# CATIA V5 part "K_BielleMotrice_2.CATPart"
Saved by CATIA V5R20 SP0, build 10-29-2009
Part number: Bielle_motrice_2
Bounding box of the stored display mesh (mm): x -195 to -75, y -122.303 to -107.303, z -65 to -35
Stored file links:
  G:\Khaled_CFAO_2011\ST2M\ST2M_GR2\jcoetard\Khaled\CAD_CATIA\K_BielleMotrice_2.CATPart
  J:\Thinkmotion\Thinkmotion_COETARD\Maquette_catia\Maquette_catia_R20_Licence_education\jcharlescoetard.CATPRODUCT\Assemblage_Pince_Prehension_Mors_Paralleles.CATProduct
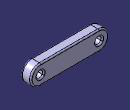
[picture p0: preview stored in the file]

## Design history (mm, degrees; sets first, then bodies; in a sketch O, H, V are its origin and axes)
Set1
  Plane1 "Plan_bielle_motrice": linked copy from another document
  Point1 "Point.11": linked copy from another document
  Point2 "Point.12": linked copy from another document
Body1 (main body)
  Sketch1 on Plane1, origin (0, -107.303, 0), H (-1, 0, 0), V (0, 0, 1)
    construction line L1 (90, -50) -> (180, -50)
    point P1 (90, -50)
    point P2 (180, -50)
    line L2 (90, -35) -> (180, -35)
    line L3 (180, -65) -> (90, -65)
    arc A1 centre (180, -50) radius 15 from (180, -35) to (180, -65) cw
    arc A2 centre (90, -50) radius 15 from (90, -65) to (90, -35) cw
    reference projected point E1 (180, -50) from Point2
    reference projected point E2 (90, -50) from Point1
    distance L2 L3 = 30
    tangency: A1 L2, A2 L2, A1 L3, A2 L3
    coincidence: P2 E1, P1 E2
  Pad1: profile Sketch1, direction (0, -1, 0), length 15
  Sketch2 on start face of Pad1, origin (-40, -107.303, -33.3333), H (1, 0, 0), V (0, 0, -1)
    point P1 (-50, 16.6667)
    reference projected point E1 (-50, 16.6667) from Point1
    coincidence: E1 P1
  Hole1: placed by Sketch2, at (-90, -107.303, -50) direction (0, -1, 0), diameter 10, depth 20
  Sketch3 on start face of Pad1, origin (-80, -107.303, -33.3333), H (1, 0, 0), V (0, 0, -1)
    point P1 (-100, 16.6667)
    reference projected point E1 (-100, 16.6667) from Point2
    coincidence: E1 P1
  Hole2: placed by Sketch3, at (-180, -107.303, -50) direction (0, -1, 0), diameter 10, depth 20
  Fillet1: radius 2, on start face of Pad1; edge [end face of Pad1 | face of Pad1 from Sketch1.A1]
